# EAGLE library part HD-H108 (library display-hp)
LED DISPLAY + - 1/2 character, decimal point right
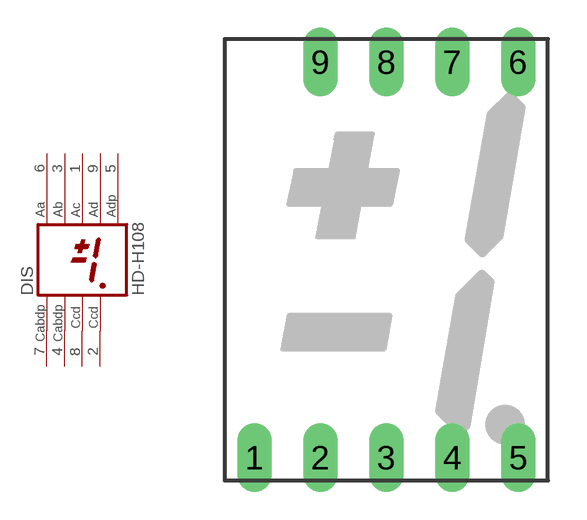
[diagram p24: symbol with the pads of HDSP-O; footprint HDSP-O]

Designator prefix DIS

## HD-H108 (OC_FARNELL: unknown; OC_NEWARK: unknown)  [HDSP-O]
1  AC  pas
2  CCD  pas
3  AB  pas
4  CABDP  pas
5  ADP  pas
6  AA  pas
7  CABDP  pas
8  CCD  pas
9  AD  pas

## Footprint HDSP-O (pad centres in mm)
LED DISPLAY 15-mm + - 1/2 character, decimal point right
drill 0.813 long: 1 -5.08,-7.62; 2 -2.54,-7.62; 3 0,-7.62; 4 2.54,-7.62; 5 5.08,-7.62; 6 5.08,7.62; 7 2.54,7.62; 8 0,7.62; 9 -2.54,7.62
